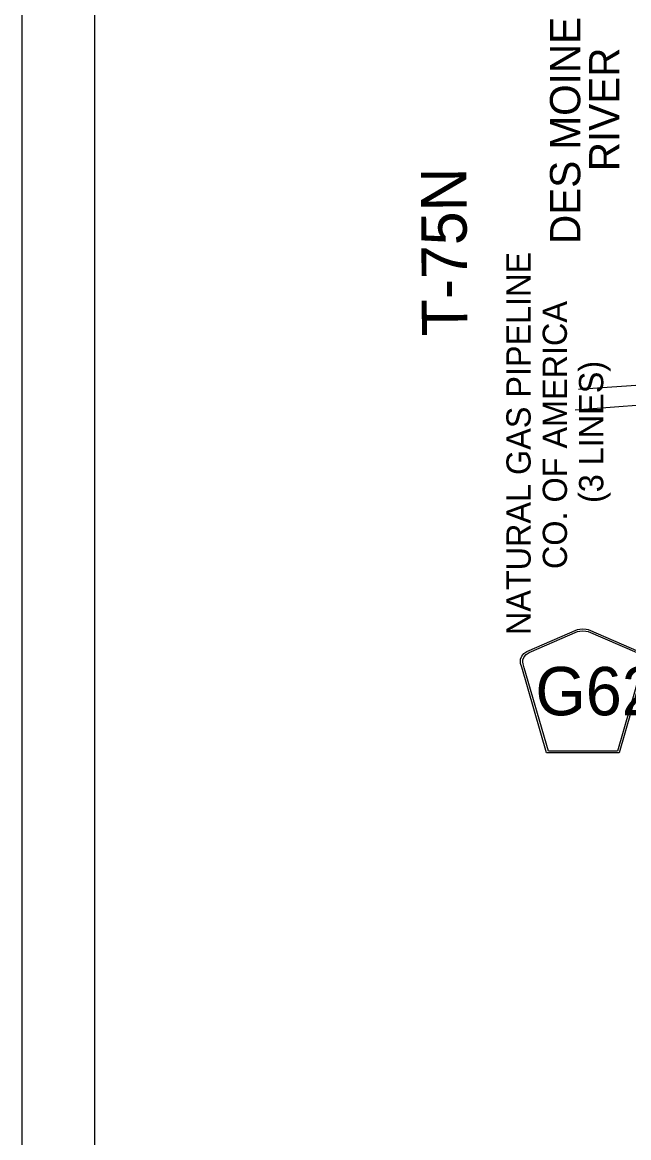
# Model space of a CAD drawing. Extents: x 23.6 to 68.7, y -63 to -29.
# Drawn here: x 30.623 to 32.626, y -51.676 to -47.991 of the extents above; entities that cross this region are included whole.
import ezdxf

# ---------------------------------------------------------------- set-up
doc = ezdxf.new("R2010")
doc.units = 0
for name, color, linetype in [('tdCoFrame', 7, 'Continuous'), ('tdCoHydroTxtLg', 7, 'Continuous'), ('tdCoPipe', 7, 'Continuous'), ('tdCoPipeTxt', 7, 'Continuous'), ('tdCoShieldCoRte', 7, 'Continuous'), ('tdCoTwpRngTxt', 7, 'Continuous')]:
    doc.layers.add(name, color=color, linetype=linetype)

msp = doc.modelspace()

# ---------------------------------------------------------------- linework, layer by layer
at = {"layer": 'tdCoFrame'}
for points in [[(30.6232, -29.9813), (66.6232, -29.9813), (66.6232, -61.9813), (30.6232, -61.9813)], [(30.8632, -30.2213), (66.3832, -30.2213), (66.3832, -61.7413), (30.8632, -61.7413)]]:
    msp.add_lwpolyline(points, close=True, dxfattribs=at)
at = {"layer": 'tdCoPipe'}
for points in [[(37.0534, -48.166), (36.1696, -48.1779), (35.5764, -48.4475), (34.7165, -48.7106), (34.096, -48.9001), (33.3916, -49.1108), (33.2198, -49.1514), (32.4609, -49.2038)], [(36.7826, -48.2843), (36.2006, -48.2399), (35.6897, -48.5144), (34.9872, -48.7211), (34.2523, -48.902), (33.7975, -49.045), (33.2588, -49.2112), (32.45, -49.2724)]]:
    msp.add_lwpolyline(points, dxfattribs=at)
at = {"layer": 'tdCoShieldCoRte'}
for points in [[(32.3553, -50.4051), (32.2734, -50.1222), (32.2695, -50.109), (32.2687, -50.1031), (32.2687, -50.0953), (32.273, -50.085), (32.2803, -50.0765), (32.2898, -50.0698), (32.4571, -49.9975), (32.4646, -49.9958), (32.4751, -49.9949), (32.4855, -49.9958), (32.493, -49.9975), (32.6603, -50.0698), (32.6698, -50.0765), (32.6771, -50.085), (32.6814, -50.0953), (32.6814, -50.1031), (32.6806, -50.109), (32.6768, -50.1222), (32.5948, -50.4051)], [(32.3612, -50.3987), (32.2814, -50.1235), (32.2777, -50.1108), (32.277, -50.1052), (32.277, -50.0977), (32.2811, -50.0878), (32.2881, -50.0796), (32.2972, -50.0732), (32.4578, -50.0038), (32.465, -50.0022), (32.4751, -50.0013), (32.4851, -50.0022), (32.4923, -50.0038), (32.6529, -50.0732), (32.6621, -50.0796), (32.669, -50.0878), (32.6731, -50.0977), (32.6731, -50.1052), (32.6724, -50.1108), (32.6687, -50.1235), (32.589, -50.3987)]]:
    msp.add_lwpolyline(points, close=True, dxfattribs=at)

# ---------------------------------------------------------------- texts
at = {"layer": 'tdCoHydroTxtLg'}
for s, p in [('DES MOINES', (32.4666, -48.7234)), ('RIVER', (32.5957, -48.483))]:
    msp.add_text(s, height=0.1, rotation=90.0233, dxfattribs=at).set_placement(p)
at = {"layer": 'tdCoPipeTxt'}
for s, p in [('NATURAL GAS PIPELINE', (32.3027, -50.0157)), ('CO. OF AMERICA', (32.4226, -49.7975)), ('(3 LINES)', (32.5425, -49.5792))]:
    msp.add_text(s, height=0.08, rotation=90.0244, dxfattribs=at).set_placement(p)
at = {"layer": 'tdCoShieldCoRte'}
msp.add_text('G62', height=0.16, dxfattribs=at).set_placement((32.3182, -50.2808))
at = {"layer": 'tdCoTwpRngTxt'}
msp.add_text('T-75N', height=0.15, rotation=90.3402, dxfattribs=at).set_placement((32.0934, -49.0279))

doc.saveas('drawing.dxf')
